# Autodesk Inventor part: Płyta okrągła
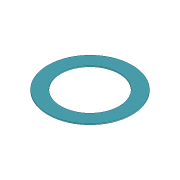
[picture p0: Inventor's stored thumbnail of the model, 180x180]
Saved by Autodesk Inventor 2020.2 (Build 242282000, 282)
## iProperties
Created: 2011-11
Part Number: Płyta okrągła
Material: Stal
Document SubType Name: Modeling
Designer: F.Stasiak
Mass: 556.733 g
Surface Area: 513.336 cm^2
Volume: 70.9215 cm^3
Density: 7.85 g/cm^3
Appearance: Niebieska z odcieniem szarości
Catalog Web Link: www.expertbooks.pl
Manager: www.cadconsulting.pl
Company: Fabian Stasiak CAD Consulting
Author: F.Stasiak
Subject: Zbiór ćwiczeń. Autodesk Inventor 2020. Kurs Professional
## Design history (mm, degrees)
sketch "Szkic1"
  geometry: C1 r 130 at (0, 0); C2 r 90 at (0, 0); 1 further point
  constraints: 2 centre point, 2 coincident
  dimensions: "d0" = 260 diameter of C1; "d1" = 180 diameter of C2
extrude "Wyciągnięcie proste1" new body sketch "Szkic1" distance "d2" = 3; taper "d3" = 0 deg
node "Bryła1"
